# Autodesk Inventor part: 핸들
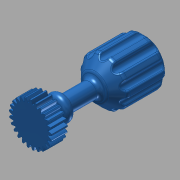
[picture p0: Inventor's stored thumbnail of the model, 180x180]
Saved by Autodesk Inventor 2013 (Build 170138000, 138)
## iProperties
Created: 2017-04
Part Number: 핸들
Material: 강철, 연강
Document SubType Name: Modeling
Designer: mduedu
Categories: <?xml version="1.0" encoding="UTF-16"?> <MemberInstance><Categories><FamilyTemplate><FamilyTemplateParameter ValueType="xs:double" Id="1" ObjectReferenceKey="da
Density: 7.86 g/cm^3
Mass: 209.327 g
Surface Area: 78.6041 cm^2
Volume: 26.6319 cm^3
CustomPartVersion: 1
Author: mduedu
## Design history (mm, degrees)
sketch "Sketch1"
  geometry: C1 r 13.5 at (0, 0)
  constraints: 1 centre point
  dimensions: "d0" = 27 diameter of C1 (= da_da)
extrude "Extrusion1" new body sketch "Sketch1" distance "d1" = 10 (= da_b); taper "d2" = 0 deg
workplane "Work Plane2"
sketch "Sketch2"
  geometry: C1 r 13.5 at (0, 0) reference; C2 r 12.5 at (0, 0)
  constraints: 1 centre point, 1 coincident
  dimensions: "d3" = 25 diameter of C2 (= da_dw)
feature "피치 지름" sketch "Sketch2" dims "d4" = 10, "d5" = 0
workplane "Work Plane8"
workplane "Work Plane9"
feature "스퍼 기어" dims "da_b" = 10, "da_d" = 25, "da_aw" = 25, "da_da" = 27, "da_df" = 22.5, "da_dw" = 25, angle "da_beta" = 0 deg, "da_lefttooth" = 0, "da_righttooth" = 0
sketch "스케치3"
  geometry: C1 r 5 at (0, 0); 1 further point
  constraints: 1 centre point, 1 coincident
  dimensions: "d49" = 10 diameter of C1
extrude "돌출2" join sketch "스케치3" distance "d50" = 60; taper "d51" = 0 deg
sketch "스케치4"
  geometry: C1 r 15 at (0, 0); 1 further point
  constraints: 1 centre point, 1 coincident
  dimensions: "d52" = 30 diameter of C1
extrude "돌출3" join sketch "스케치4" distance "d53" = 30; taper "d54" = 0 deg
chamfer "모따기1" distance "d55" = 7; stored, may be unused: second distance "d56" = 2, angle "d57" = 45 deg
sketch "스케치5"
  geometry: L1 (0, 2.2)-(0, -13.2) reference; L2 (0, -5)-(8, -5); L3 (8, -5)-(8, -11); L4 (8, -11)-(0, -11); L5 (0, -11)-(0, -5); 1 further point
  constraints: 8 end point, 2 parallel, 1 horizontal, 1 perpendicular, 1 point on line
  dimensions: "d58" = 5 distance from line of L2 point (0, 0); "d59" = 6 distance of L2.end L3.end; "d60" = 16 diameter of L3 L1
revolve "회전1" sketch "스케치5" stored, may be unused: angle "d61" = 90 deg
fillet "모깎기1" dims "d62" = 3
fillet "모깎기2" dims "d65" = 3
sketch "스케치9"
  geometry: L1 (15, -60)-(-15, -60) reference; L2 (0, -60)-(0, 0); L3 (0, -66.771)-(0, -60); A1 r 20 centre (0, -46.771) between (0, -66.771) and (15, -60)
  constraints: 4 end point, 2 point on circle, 1 centre point, 1 collinear, 1 line through centre, 1 midpoint, 1 perpendicular
  dimensions: "d84" = 20 radius of A1
revolve "회전4" sketch "스케치9" stored, may be unused: angle "d86" = 90 deg
fillet "모깎기3" dims "d72" = 3
sketch "스케치6"
  geometry: C1 r 2.5 at (0, 15); 2 further points
  constraints: 2 vertical alignment, 1 centre point, 1 other
  dimensions: "d66" = 5 diameter of C1
extrude "돌출4" cut sketch "스케치6" stored distance "d67" = 60; taper "d68" = 0 deg
fillet "모깎기4" dims "d73" = 1
node "작업 평면12"
sketch "스케치10"
  geometry: C1 r 6 at (0, 0); 1 further point
  constraints: 1 centre point, 1 coincident
  dimensions: "d87" = 12 diameter of C1
extrude "돌출5" cut sketch "스케치10" distance "d88" = 5; taper "d89" = 0 deg
fillet "모깎기5" dims "d90" = 1
body "Solid1"
pattern_circular "원형 패턴2" dims angle "d75" = 360 deg
body "Srf1"
other parameters: "d16" = 25 (= da_aw), "d17" = 0, "d34" = 1.25664 (computed from da_z), "d39" = 0, "d41" = 0, "d43" = 25 (= da_aw), "d46" = 25 (= da_aw), "d47" = 0, "d48" = 0
